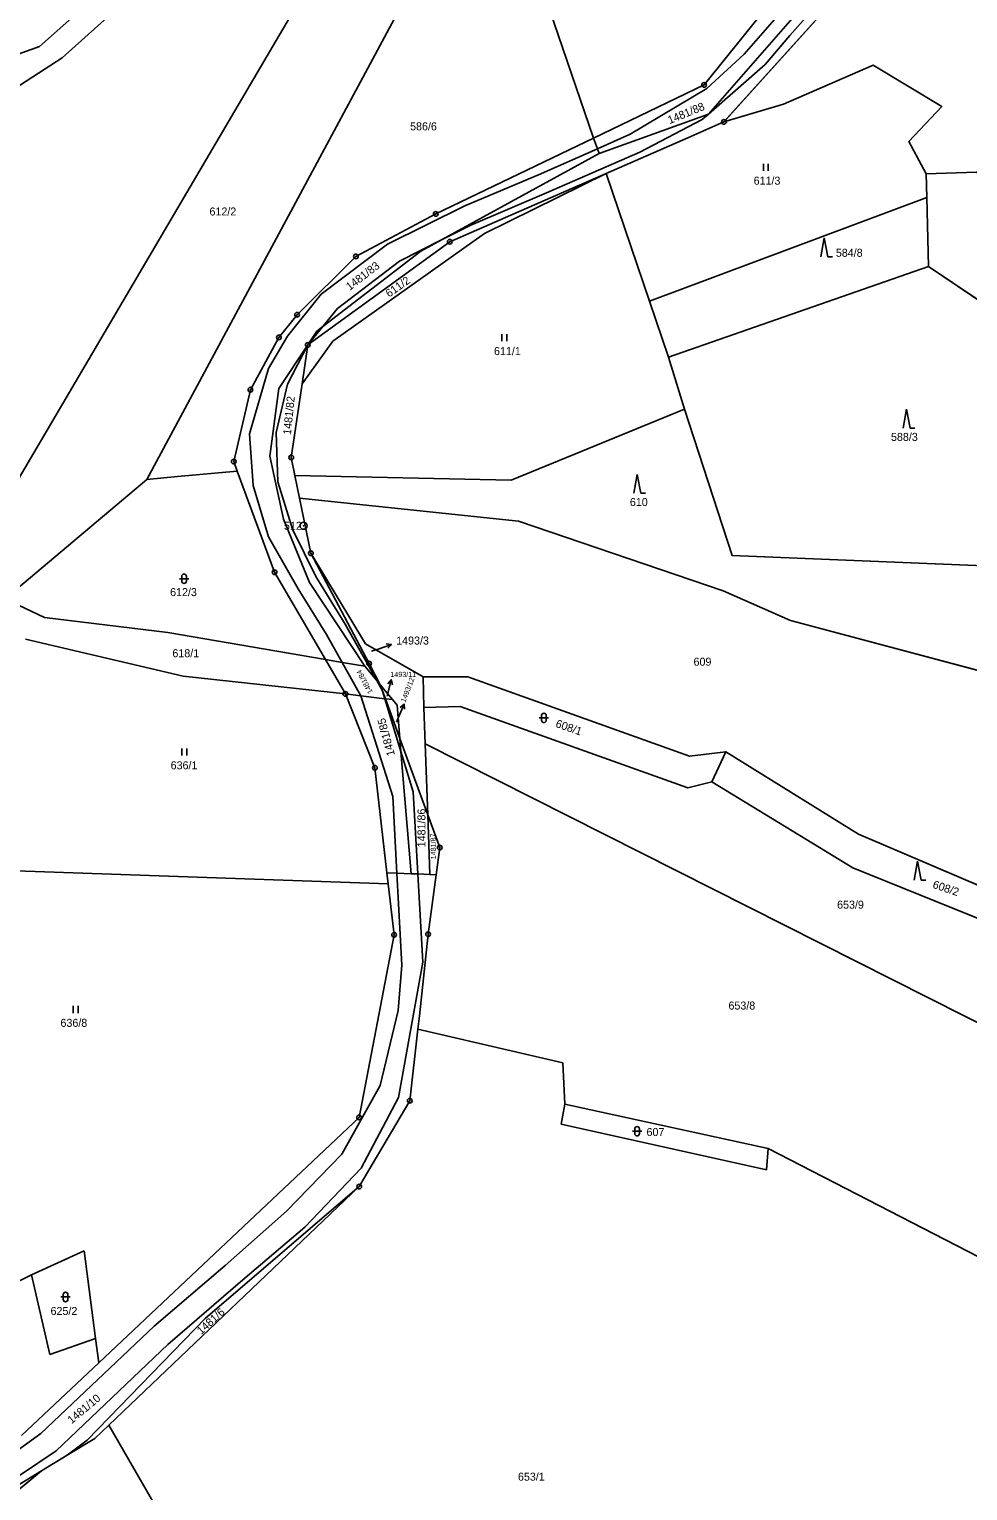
# Model space of a CAD drawing. Extents: x -760642 to -757221, y -1092371 to -1088855.
# Drawn here: x -760077.8 to -759878.4, y -1090551.6 to -1090241.2 of the extents above; entities that cross this region are included whole.
import ezdxf

# ---------------------------------------------------------------- set-up
doc = ezdxf.new("R2010")
doc.units = 0
for name, color, linetype in [('Vrstva 1', 7, 'Continuous'), ('Vrstva 16', 7, 'Continuous'), ('Vrstva 17', 7, 'Continuous'), ('Vrstva 18', 7, 'Continuous'), ('Vrstva 24', 7, 'Continuous'), ('Vrstva 25', 7, 'Continuous'), ('Vrstva 30', 7, 'Continuous'), ('Vrstva 4', 7, 'Continuous')]:
    doc.layers.add(name, color=color, linetype=linetype)

msp = doc.modelspace()

# ---------------------------------------------------------------- linework, layer by layer
at = {"layer": 'Vrstva 1'}
for p, q in [((-760080.17, -1090336.84), (-759987.2, -1090178.61)), ((-760052.84, -1090336.84), (-759979.66, -1090200.65)), ((-759957.88, -1090264.31), (-759979.66, -1090200.65)), ((-760044.04, -1090216.77), (-760075.65, -1090244.9)), ((-759934.42, -1090253.04), (-759908.17, -1090220.5)), ((-759895.76, -1090222.67), (-759930.18, -1090260.9)), ((-760044.75, -1090223.87), (-760070.8, -1090247.3)), ((-759906.89, -1090228.8), (-759933.47, -1090259.21)), ((-760075.65, -1090244.9), (-760087.13, -1090249)), ((-760070.8, -1090247.3), (-760108.98, -1090271.91)), ((-759917.51, -1090257.14), (-759898.46, -1090248.84)), ((-759898.46, -1090248.84), (-759883.89, -1090257.58)), ((-759957.88, -1090264.31), (-759934.42, -1090253.04)), ((-759930.18, -1090260.9), (-759917.51, -1090257.14)), ((-759956.72, -1090267.62), (-759933.47, -1090259.21)), ((-759883.89, -1090257.58), (-759890.91, -1090265.03)), ((-759937.87, -1090264.26), (-759930.18, -1090260.9)), ((-759991.44, -1090280.43), (-759957.88, -1090264.31)), ((-759957.88, -1090264.31), (-759957.08, -1090266.6)), ((-759957.08, -1090266.6), (-759956.72, -1090267.62)), ((-759955.25, -1090271.84), (-759937.87, -1090264.26)), ((-759890.91, -1090265.03), (-759887.2, -1090271.94)), ((-759956.72, -1090267.62), (-759990.24, -1090285.94)), ((-759988.45, -1090286.33), (-759955.25, -1090271.84)), ((-759981.07, -1090284.61), (-759955.25, -1090271.84)), ((-759955.25, -1090271.84), (-759946.03, -1090298.92)), ((-759887.2, -1090271.94), (-759876.5, -1090271.55)), ((-759887.2, -1090271.94), (-759887.08, -1090276.95)), ((-759946.03, -1090298.92), (-759887.08, -1090276.95)), ((-759887.08, -1090276.95), (-759886.74, -1090291.57)), ((-760008.38, -1090289.44), (-759991.44, -1090280.43)), ((-760013.33, -1090307.48), (-759981.07, -1090284.61)), ((-759988.45, -1090286.33), (-760018.63, -1090308.24)), ((-759994.63, -1090288.34), (-760015.45, -1090304.35)), ((-759990.24, -1090285.94), (-759994.63, -1090288.34)), ((-760020.9, -1090301.84), (-760008.38, -1090289.44)), ((-759941.98, -1090310.83), (-759886.74, -1090291.57)), ((-759886.74, -1090291.57), (-759819.96, -1090336.6)), ((-759946.03, -1090298.92), (-759941.98, -1090310.83)), ((-760020.9, -1090301.84), (-760024.75, -1090306.65)), ((-760024.75, -1090306.65), (-760030.82, -1090317.75)), ((-760016.68, -1090305.3), (-760018.63, -1090308.24)), ((-760015.45, -1090304.35), (-760016.68, -1090305.3)), ((-760024.77, -1090317.5), (-760018.63, -1090308.24)), ((-760013.33, -1090307.48), (-760019.84, -1090316.48)), ((-760019.84, -1090316.48), (-760018.63, -1090308.24)), ((-759938.58, -1090321.86), (-759941.98, -1090310.83)), ((-760030.82, -1090317.75), (-760034.35, -1090333.01)), ((-760024.77, -1090317.5), (-760026.71, -1090331.89)), ((-760022.14, -1090332.15), (-760019.84, -1090316.48)), ((-759975.38, -1090336.95), (-759938.58, -1090321.86)), ((-759928.46, -1090352.96), (-759938.58, -1090321.86)), ((-760034.35, -1090333.01), (-760033.61, -1090335.02)), ((-760026.71, -1090331.89), (-760023.81, -1090345.26)), ((-760021.35, -1090335.96), (-760022.14, -1090332.15)), ((-760082.91, -1090362.19), (-760052.84, -1090336.84)), ((-760052.84, -1090336.84), (-760046.28, -1090336.22)), ((-760046.28, -1090336.22), (-760033.61, -1090335.02)), ((-760033.61, -1090335.02), (-760025.67, -1090356.53)), ((-760021.35, -1090335.96), (-759975.38, -1090336.95)), ((-760020.35, -1090340.8), (-760021.35, -1090335.96)), ((-760020.35, -1090340.8), (-759973.81, -1090345.64)), ((-760017.95, -1090352.48), (-760020.35, -1090340.8)), ((-760023.81, -1090345.26), (-760018.28, -1090358.73)), ((-759973.81, -1090345.64), (-759930.34, -1090360.5)), ((-760005.58, -1090375.93), (-760017.95, -1090352.48)), ((-760006.34, -1090371.69), (-760017.95, -1090352.48)), ((-759928.46, -1090352.96), (-759843.88, -1090356.4)), ((-760025.67, -1090356.53), (-760014.89, -1090375.05)), ((-760018.28, -1090358.73), (-760006.49, -1090376.49)), ((-760082.91, -1090362.19), (-760074.59, -1090366.12)), ((-759930.34, -1090360.5), (-759916.02, -1090366.78)), ((-760074.59, -1090366.12), (-760048.39, -1090369.3)), ((-759916.02, -1090366.78), (-759855.09, -1090383)), ((-760078.6, -1090370.71), (-760045.11, -1090378.59)), ((-760048.39, -1090369.3), (-760014.89, -1090375.05)), ((-759994.13, -1090378.75), (-760006.34, -1090371.69)), ((-760014.89, -1090375.05), (-760011.33, -1090375.66)), ((-760014.89, -1090375.05), (-760010.64, -1090382.35)), ((-760011.33, -1090375.66), (-760006.49, -1090376.49)), ((-760006.49, -1090376.49), (-760003.96, -1090379.52)), ((-760003.21, -1090380.42), (-760005.58, -1090375.93)), ((-760045.11, -1090378.59), (-760010.64, -1090382.35)), ((-760003.96, -1090379.52), (-760003.21, -1090380.42)), ((-760002.13, -1090383.39), (-760003.21, -1090380.42)), ((-760000.64, -1090383.57), (-760003.21, -1090380.42)), ((-759994.13, -1090378.75), (-759984.62, -1090378.73)), ((-759994.13, -1090378.75), (-759993.93, -1090385.24)), ((-759984.62, -1090378.73), (-759937.53, -1090395.56)), ((-760010.64, -1090382.35), (-760007.37, -1090382.75)), ((-760010.64, -1090382.35), (-760004.37, -1090398.03)), ((-760007.37, -1090382.75), (-760002.27, -1090383.37)), ((-760002.27, -1090383.37), (-760002.13, -1090383.39)), ((-760002.13, -1090383.39), (-760000.64, -1090383.57)), ((-759999.06, -1090391.8), (-760002.13, -1090383.39)), ((-760000.64, -1090383.57), (-759999.65, -1090384.77)), ((-759999.65, -1090384.77), (-759999.06, -1090391.8)), ((-759993.93, -1090385.24), (-759986.22, -1090385.01)), ((-759993.93, -1090385.24), (-759993.69, -1090392.97)), ((-759986.22, -1090385.01), (-759937.87, -1090402.28)), ((-759999.06, -1090391.8), (-759998.82, -1090394.62)), ((-759993.13, -1090408.07), (-759999.06, -1090391.8)), ((-759993.69, -1090392.97), (-759841.28, -1090469.87)), ((-759993.69, -1090392.97), (-759993.13, -1090408.07)), ((-759998.82, -1090394.62), (-759996.66, -1090420.54)), ((-759937.53, -1090395.56), (-759929.79, -1090394.64)), ((-759929.79, -1090394.64), (-759932.73, -1090401)), ((-759929.79, -1090394.64), (-759901.58, -1090412.15)), ((-760004.37, -1090398.03), (-760001.8, -1090420.34)), ((-759937.87, -1090402.28), (-759932.73, -1090401)), ((-759932.73, -1090401), (-759902.82, -1090419.3)), ((-759993.13, -1090408.07), (-759992.66, -1090420.7)), ((-759990.59, -1090415), (-759993.13, -1090408.07)), ((-759901.58, -1090412.15), (-759854.8, -1090432.12)), ((-759991.36, -1090420.75), (-759990.59, -1090415)), ((-760088.84, -1090419.64), (-760001.53, -1090422.66)), ((-760001.8, -1090420.34), (-759999.67, -1090420.42)), ((-760001.8, -1090420.34), (-760001.53, -1090422.66)), ((-759999.67, -1090420.42), (-759996.66, -1090420.54)), ((-759996.66, -1090420.54), (-759995.24, -1090420.6)), ((-759995.24, -1090420.6), (-759992.66, -1090420.7)), ((-759993.06, -1090433.39), (-759991.36, -1090420.75)), ((-759992.66, -1090420.7), (-759991.36, -1090420.75)), ((-759902.82, -1090419.3), (-759855.28, -1090438.48)), ((-760001.53, -1090422.66), (-760000.28, -1090433.5)), ((-760000.28, -1090433.5), (-760007.72, -1090472.28)), ((-759994.91, -1090450.69), (-759993.06, -1090433.39)), ((-759994.91, -1090450.69), (-759995.23, -1090453.54)), ((-759995.23, -1090453.54), (-759996.96, -1090468.77)), ((-759995.23, -1090453.54), (-759964.45, -1090460.73)), ((-759963.98, -1090469.51), (-759964.45, -1090460.73)), ((-760007.69, -1090486.97), (-759996.96, -1090468.77)), ((-759963.98, -1090469.51), (-759964.75, -1090473.7)), ((-759963.98, -1090469.51), (-759920.78, -1090478.92)), ((-760007.72, -1090472.28), (-760063.02, -1090524.4)), ((-759964.75, -1090473.7), (-759921.17, -1090483.4)), ((-759921.17, -1090483.4), (-759920.78, -1090478.92)), ((-759920.78, -1090478.92), (-759870.1, -1090505.04)), ((-760060.93, -1090537.68), (-760007.69, -1090486.97)), ((-760040.37, -1090514.93), (-760007.69, -1090486.97)), ((-760066.16, -1090500.6), (-760077.32, -1090505.75)), ((-760066.16, -1090500.6), (-760063.7, -1090519.23)), ((-760077.32, -1090505.75), (-760095.56, -1090514.7)), ((-760077.32, -1090505.75), (-760073.41, -1090522.65)), ((-760065.48, -1090540.8), (-760040.37, -1090514.93)), ((-760073.41, -1090522.65), (-760063.7, -1090519.23)), ((-760063.7, -1090519.23), (-760063.02, -1090524.4)), ((-760063.02, -1090524.4), (-760079.42, -1090539.86)), ((-760063.87, -1090540.48), (-760060.93, -1090537.68)), ((-760051.34, -1090554.19), (-760060.93, -1090537.68)), ((-760069.73, -1090544.04), (-760063.87, -1090540.48)), ((-760069.73, -1090544.04), (-760065.48, -1090540.8)), ((-760075.22, -1090547.37), (-760069.73, -1090544.04)), ((-760092.34, -1090561.46), (-760075.22, -1090547.37)), ((-760080.9, -1090550.82), (-760075.22, -1090547.37))]:
    msp.add_line(p, q, dxfattribs=at)
at = {"layer": 'Vrstva 16'}
for p, q in [((-760003.68, -1090372.83), (-760000.839, -1090371.865)), ((-760005.08, -1090373.31), (-760003.68, -1090372.83)), ((-760001.61, -1090382.27), (-760000.892, -1090379.357)), ((-760001.75, -1090382.85), (-760001.61, -1090382.27)), ((-759999.31, -1090387.28), (-759998.148, -1090384.514)), ((-759999.78, -1090388.39), (-759999.31, -1090387.28))]:
    msp.add_line(p, q, dxfattribs=at)
for points in [[(-760001.947, -1090371.713), (-760000.839, -1090371.865), (-760001.625, -1090372.66)], [(-760001.617, -1090380.208), (-760000.892, -1090379.357), (-760000.646, -1090380.448)], [(-759998.996, -1090385.242), (-759998.148, -1090384.514), (-759998.074, -1090385.63)]]:
    msp.add_lwpolyline(points, dxfattribs=at)
at = {"layer": 'Vrstva 24'}
for centre, radius in [((-759934.42, -1090253.04), 0.5), ((-759934.42, -1090253.04), 0.0327), ((-759930.18, -1090260.9), 0.5), ((-759930.18, -1090260.9), 0.0327), ((-759991.44, -1090280.43), 0.5), ((-759991.44, -1090280.43), 0.0327), ((-759988.45, -1090286.33), 0.5), ((-759988.45, -1090286.33), 0.0327), ((-760008.38, -1090289.44), 0.5), ((-760008.38, -1090289.44), 0.0327), ((-760020.9, -1090301.84), 0.5), ((-760020.9, -1090301.84), 0.0327), ((-760024.75, -1090306.65), 0.5), ((-760024.75, -1090306.65), 0.0327), ((-760018.63, -1090308.24), 0.5), ((-760018.63, -1090308.24), 0.0327), ((-760030.82, -1090317.75), 0.5), ((-760030.82, -1090317.75), 0.0327), ((-760022.14, -1090332.15), 0.5), ((-760034.35, -1090333.01), 0.5), ((-760034.35, -1090333.01), 0.0327), ((-760022.14, -1090332.15), 0.0327), ((-760019.52, -1090346.65), 0.75), ((-760019.52, -1090346.65), 0.0327), ((-760017.95, -1090352.48), 0.5), ((-760017.95, -1090352.48), 0.0327), ((-760025.67, -1090356.53), 0.5), ((-760025.67, -1090356.53), 0.0327), ((-760005.58, -1090375.93), 0.5), ((-760005.58, -1090375.93), 0.0327), ((-760010.64, -1090382.35), 0.5), ((-760010.64, -1090382.35), 0.0327), ((-760004.37, -1090398.03), 0.5), ((-760004.37, -1090398.03), 0.0327), ((-759990.59, -1090415), 0.5), ((-759990.59, -1090415), 0.0327), ((-760000.28, -1090433.5), 0.5), ((-760000.28, -1090433.5), 0.0327), ((-759993.06, -1090433.39), 0.5), ((-759993.06, -1090433.39), 0.0327), ((-759996.96, -1090468.77), 0.5), ((-759996.96, -1090468.77), 0.0327), ((-760007.72, -1090472.28), 0.5), ((-760007.72, -1090472.28), 0.0327), ((-760007.69, -1090486.97), 0.5), ((-760007.69, -1090486.97), 0.0327)]:
    msp.add_circle(centre, radius, dxfattribs=at)
at = {"layer": 'Vrstva 25'}
for p, q in [((-759921.807, -1090269.785), (-759921.807, -1090271.285)), ((-759920.785, -1090271.285), (-759920.785, -1090269.785)), ((-759908.872, -1090285.519), (-759909.605, -1090289.519)), ((-759908.872, -1090285.519), (-759908.139, -1090289.519)), ((-759908.139, -1090289.519), (-759907.139, -1090289.519)), ((-759977.357, -1090305.975), (-759977.357, -1090307.475)), ((-759976.335, -1090307.475), (-759976.335, -1090305.975)), ((-759891.362, -1090321.919), (-759892.095, -1090325.919)), ((-759891.362, -1090321.919), (-759890.629, -1090325.919)), ((-759890.629, -1090325.919), (-759889.629, -1090325.919)), ((-759948.602, -1090335.749), (-759949.335, -1090339.749)), ((-759948.602, -1090335.749), (-759947.869, -1090339.749)), ((-759947.869, -1090339.749), (-759946.869, -1090339.749)), ((-760045.91, -1090357.89), (-760043.91, -1090357.89)), ((-760045.41, -1090358.39), (-760045.41, -1090357.39)), ((-760044.41, -1090358.39), (-760044.41, -1090357.39)), ((-759969.44, -1090387.46), (-759967.44, -1090387.46)), ((-759968.94, -1090387.96), (-759968.94, -1090386.96)), ((-759967.94, -1090387.96), (-759967.94, -1090386.96)), ((-760045.377, -1090393.935), (-760045.377, -1090395.435)), ((-760044.355, -1090395.435), (-760044.355, -1090393.935)), ((-759889.032, -1090417.899), (-759889.765, -1090421.899)), ((-759889.032, -1090417.899), (-759888.299, -1090421.899)), ((-759888.299, -1090421.899), (-759887.299, -1090421.899)), ((-760068.457, -1090448.625), (-760068.457, -1090450.125)), ((-760067.435, -1090450.125), (-760067.435, -1090448.625)), ((-759949.64, -1090475.24), (-759947.64, -1090475.24)), ((-759949.14, -1090475.74), (-759949.14, -1090474.74)), ((-759948.14, -1090475.74), (-759948.14, -1090474.74)), ((-760071.1, -1090510.43), (-760069.1, -1090510.43)), ((-760070.6, -1090510.93), (-760070.6, -1090509.93)), ((-760069.6, -1090510.93), (-760069.6, -1090509.93))]:
    msp.add_line(p, q, dxfattribs=at)
for centre, start, end in [((-760044.91, -1090357.39), 0, 180), ((-760044.91, -1090358.39), 180, 0), ((-759968.44, -1090386.96), 0, 180), ((-759968.44, -1090387.96), 180, 0), ((-759948.64, -1090474.74), 0, 180), ((-759948.64, -1090475.74), 180, 0), ((-760070.1, -1090509.93), 0, 180), ((-760070.1, -1090510.93), 180, 0)]:
    msp.add_arc(centre, 0.5, start, end, dxfattribs=at)
at = {"layer": 'Vrstva 30'}
for points in [[(-759929.701, -1090260.758), (-759917.51, -1090257.14), (-759898.46, -1090248.84), (-759883.89, -1090257.58), (-759890.91, -1090265.03), (-759887.2, -1090271.94), (-759876.5, -1090271.55), (-759822.14, -1090310.19), (-759806.41, -1090317.19), (-759797.43, -1090302.2), (-759795.55, -1090289.48), (-759792.77, -1090256.83), (-759785.94, -1090251.03), (-759773.19, -1090248.13), (-759770.83, -1090226.08), (-759765.77, -1090190.22), (-759764.68, -1090183.57), (-759879.39, -1090234.5), (-759885.88, -1090220.12), (-759893.47, -1090219.66), (-759895.457, -1090222.272)], [(-759896.095, -1090223.042), (-759929.845, -1090260.528)], [(-759819.96, -1090336.6), (-759816.36, -1090333.8), (-759806.41, -1090317.19), (-759822.14, -1090310.19), (-759876.5, -1090271.55), (-759887.2, -1090271.94), (-759887.08, -1090276.95), (-759886.74, -1090291.57), (-759819.96, -1090336.6)], [(-759886.74, -1090291.57), (-759887.08, -1090276.95), (-759946.03, -1090298.92), (-759941.98, -1090310.83), (-759886.74, -1090291.57)], [(-759886.74, -1090291.57), (-759941.98, -1090310.83), (-759938.58, -1090321.86), (-759928.46, -1090352.96), (-759843.88, -1090356.4), (-759819.96, -1090336.6), (-759886.74, -1090291.57)], [(-759843.88, -1090356.4), (-759928.46, -1090352.96), (-759938.58, -1090321.86), (-759975.38, -1090336.95), (-760021.35, -1090335.96), (-760020.35, -1090340.8), (-759973.81, -1090345.64), (-759930.34, -1090360.5), (-759916.02, -1090366.78), (-759855.09, -1090383), (-759843.88, -1090356.4)], [(-759819.5, -1090442.84), (-759815.4, -1090437.75), (-759835.37, -1090437.86), (-759854.8, -1090432.12), (-759901.58, -1090412.15), (-759929.79, -1090394.64), (-759932.73, -1090401), (-759902.82, -1090419.3), (-759855.28, -1090438.48), (-759835.32, -1090442.96), (-759819.5, -1090442.84)], [(-760087.49, -1090727.12), (-760065.45, -1090685.86), (-760059.44, -1090691.57), (-760059.06, -1090689.48), (-760059.059, -1090689.475), (-760053.78, -1090660.88), (-760047.65, -1090627.66), (-760061.65, -1090617.23), (-760065.98, -1090601.05), (-760076.56, -1090576.6), (-760058.3, -1090573.38), (-760061.5, -1090554.05), (-760051.34, -1090554.19), (-760060.93, -1090537.68), (-760063.87, -1090540.48), (-760069.73, -1090544.04), (-760075.22, -1090547.37), (-760092.34, -1090561.46)]]:
    msp.add_lwpolyline(points, dxfattribs=at)
msp.add_arc((-759930.18, -1090260.9), 0.5, 16.52899, 48.00203, dxfattribs=at)
at = {"layer": 'Vrstva 4'}
for p, q in [((-759895.82, -1090219.52), (-759916.17, -1090242.53)), ((-759925.89, -1090246.53), (-759918.98, -1090238.55)), ((-759916.17, -1090242.53), (-759921.42, -1090248.72)), ((-759933.81, -1090253.77), (-759925.89, -1090246.53)), ((-759921.42, -1090248.72), (-759933.47, -1090259.21)), ((-759950.11, -1090263.52), (-759933.81, -1090253.77)), ((-759934.85, -1090260.41), (-759948.06, -1090267.32)), ((-759933.47, -1090259.21), (-759934.85, -1090260.41)), ((-759957.08, -1090266.6), (-759950.11, -1090263.52)), ((-759969.61, -1090272.14), (-759957.08, -1090266.6)), ((-759948.06, -1090267.32), (-759967.89, -1090275.94)), ((-759985.23, -1090278.68), (-759969.61, -1090272.14)), ((-759967.89, -1090275.94), (-759983.98, -1090282.79)), ((-760001.7, -1090286.86), (-759985.23, -1090278.68)), ((-759983.98, -1090282.79), (-759990.24, -1090285.94)), ((-760015.81, -1090297.44), (-760001.7, -1090286.86)), ((-759990.24, -1090285.94), (-759999.16, -1090290.43)), ((-759999.16, -1090290.43), (-760012.31, -1090300.52)), ((-760022.95, -1090306.37), (-760015.81, -1090297.44)), ((-760012.31, -1090300.52), (-760015.45, -1090304.35)), ((-760027, -1090313.26), (-760022.95, -1090306.37)), ((-760015.45, -1090304.35), (-760018.63, -1090308.24)), ((-760018.63, -1090308.24), (-760022.96, -1090316.57)), ((-760031.03, -1090327.15), (-760027, -1090313.26)), ((-760022.96, -1090316.57), (-760025.32, -1090326.83)), ((-760030.2, -1090338.07), (-760031.03, -1090327.15)), ((-760025.32, -1090326.83), (-760025, -1090337.31)), ((-760025, -1090337.31), (-760021.85, -1090347.35)), ((-760026.96, -1090348.97), (-760030.2, -1090338.07)), ((-760021.85, -1090347.35), (-760016.91, -1090357.41)), ((-760020.64, -1090360.01), (-760026.96, -1090348.97)), ((-760016.91, -1090357.41), (-760010.65, -1090367.53)), ((-760014.65, -1090369.71), (-760020.64, -1090360.01)), ((-760003.96, -1090379.52), (-760010.65, -1090367.53)), ((-760011.33, -1090375.66), (-760014.65, -1090369.71)), ((-760007.37, -1090382.75), (-760011.33, -1090375.66)), ((-760002.83, -1090381.55), (-760003.96, -1090379.52)), ((-760000.57, -1090404.14), (-760007.37, -1090382.75)), ((-760002.83, -1090381.55), (-760002.27, -1090383.37)), ((-760002.27, -1090383.37), (-759998.82, -1090394.62)), ((-759998.82, -1090394.62), (-759996.21, -1090403.16)), ((-759996.21, -1090403.16), (-759995.24, -1090420.6)), ((-759999.67, -1090420.42), (-760000.57, -1090404.14)), ((-759998.6, -1090439.98), (-759999.67, -1090420.42)), ((-759995.24, -1090420.6), (-759994.19, -1090439.3)), ((-759999.39, -1090449.56), (-759998.6, -1090439.98)), ((-759994.19, -1090439.3), (-759999.32, -1090468.05)), ((-760003.26, -1090465.51), (-759999.39, -1090449.56)), ((-760011.36, -1090480.07), (-760003.26, -1090465.51)), ((-759999.32, -1090468.05), (-760007.26, -1090483.07)), ((-760023.14, -1090492.21), (-760011.36, -1090480.07)), ((-760007.26, -1090483.07), (-760019.25, -1090495.58)), ((-760036.18, -1090503.77), (-760023.14, -1090492.21)), ((-760019.25, -1090495.58), (-760032.39, -1090506.76)), ((-760051.27, -1090516.61), (-760036.18, -1090503.77)), ((-760032.39, -1090506.76), (-760048.33, -1090520.53)), ((-760075.38, -1090539.44), (-760051.27, -1090516.61)), ((-760048.33, -1090520.53), (-760072.12, -1090543.1)), ((-760086.5, -1090547.43), (-760075.38, -1090539.44)), ((-760072.12, -1090543.1), (-760084.04, -1090551.07))]:
    msp.add_line(p, q, dxfattribs=at)

# ---------------------------------------------------------------- texts
at = {"layer": 'Vrstva 16'}
for s, height, p in [('1493/3', 1.7, (-759999.84, -1090371.87)), ('1493/11', 1.1, (-760001.08, -1090378.77))]:
    msp.add_text(s, height=height, dxfattribs=at).set_placement(p)
msp.add_text('1493/12', height=1.1, rotation=68.9625, dxfattribs=at).set_placement((-759997.89, -1090384.25))
at = {"layer": 'Vrstva 17'}
msp.add_text('512', height=1.7, dxfattribs=at).set_placement((-760023.681, -1090347.5))
at = {"layer": 'Vrstva 18'}
for s, height, rotation, p in [('1481/88', 1.7, 22.41, (-759941.72, -1090261.37)), ('1481/83', 1.7, 37.61208, (-760009.7, -1090296.78)), ('611/2', 1.7, 35.12061, (-760001.34, -1090298.22)), ('1481/82', 1.7, 84.21525, (-760022.2, -1090327.39)), ('1493/3', 0.1, 91.03221, (-760005.08, -1090373.31)), ('1481/84', 1.1, 117.89406, (-760004.77, -1090381.97)), ('1481/85', 1.7, 105.06294, (-760000.09, -1090395.29)), ('1493/12', 0.1, 90, (-759999.78, -1090388.566)), ('608/1', 1.7, 340.86798, (-759966.1, -1090389.34)), ('1481/86', 1.7, 90, (-759993.61, -1090414.94)), ('1481/87', 1.1, 91.01394, (-759991.36, -1090417.47)), ('608/2', 1.7, 341.37846, (-759885.98, -1090423.5)), ('1481/6', 1.7, 41.87178, (-760041.27, -1090518.51)), ('1481/10', 1.7, 39.74805, (-760068.813, -1090537.466))]:
    msp.add_text(s, height=height, rotation=rotation, dxfattribs=at).set_placement(p)
for s, height, p in [('586/6', 1.7, (-759996.88, -1090262.68)), ('611/3', 1.7, (-759923.88, -1090274.22)), ('612/2', 1.7, (-760039.51, -1090280.76)), ('584/8', 1.7, (-759906.41, -1090289.53)), ('611/1', 1.7, (-759979.05, -1090310.41)), ('588/3', 1.7, (-759894.69, -1090328.63)), ('610', 1.7, (-759950.18, -1090342.46)), ('612/3', 1.7, (-760047.874, -1090361.59)), ('618/1', 1.7, (-760047.39, -1090374.57)), ('609', 1.7, (-759936.648, -1090376.37)), ('1493/11', 0.1, (-760001.908, -1090382.85)), ('636/1', 1.7, (-760047.76, -1090398.37)), ('653/9', 1.7, (-759906.14, -1090427.96)), ('653/8', 1.7, (-759929.23, -1090449.39)), ('636/8', 1.7, (-760071.174, -1090453.06)), ('607', 1.7, (-759946.64, -1090476.24)), ('625/2', 1.7, (-760073.28, -1090514.25)), ('653/1', 1.7, (-759973.96, -1090549.44))]:
    msp.add_text(s, height=height, dxfattribs=at).set_placement(p)

doc.saveas('drawing.dxf')
